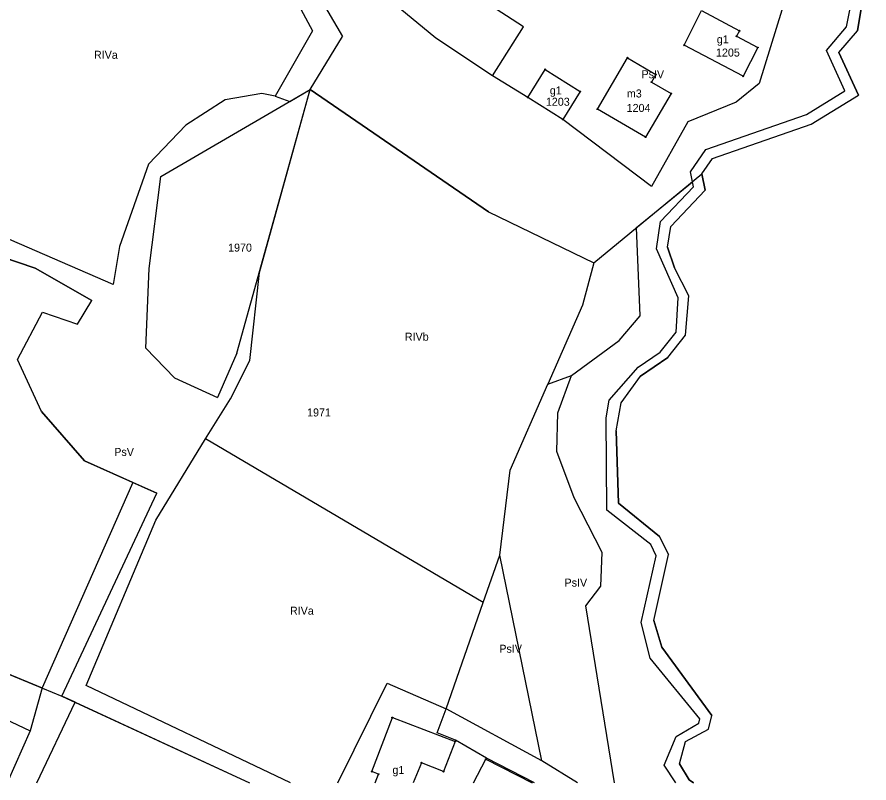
# Model space of a CAD drawing. Extents: x 7498273 to 7499989, y 5499795 to 5500810.
# Drawn here: x 7499569.7 to 7499729.3, y 5499795 to 5499938.6 of the extents above; entities that cross this region are included whole.
import ezdxf

# ---------------------------------------------------------------- set-up
doc = ezdxf.new("R2010")
doc.units = 0
for name, color, linetype in [('209-oznaczenie konturu klasyfikacyjnego', 7, 'Continuous'), ('211-numer działki ewidencyjnej', 7, 'Continuous'), ('217-kontur klasyfikacyjny', 7, 'Continuous'), ('218-kontur użytku gruntowego', 7, 'Continuous'), ('219-działka ewidencyjna', 7, 'Continuous'), ('312-budynek ewidencyjny', 7, 'Continuous'), ('312-oznaczenie budynku ewidencyjnego', 7, 'Continuous'), ('312-oznaczenie budynku ewidencyjnego-Atr117', 7, 'Continuous'), ('Punkt budynku', 7, 'Continuous')]:
    doc.layers.add(name, color=color, linetype=linetype)

# ---------------------------------------------------------------- blocks, each defined once
blk = doc.blocks.new('PUNKTBUD')
blk.add_circle((0, 0), 0.09)

msp = doc.modelspace()

# ---------------------------------------------------------------- linework, layer by layer
at = {"layer": '217-kontur klasyfikacyjny'}
for points in [[(7499648.19, 5499934.62), (7499630.46, 5499949.31)], [(7499619.31, 5499946.76), (7499625.09, 5499936)], [(7499725.13, 5499936.77), (7499727.33, 5499947.8)], [(7499714.09, 5499943.34), (7499708.75, 5499926.13)], [(7499664.64, 5499936.76), (7499657.35, 5499941.41)], [(7499625.09, 5499936), (7499618.09, 5499923.72)], [(7499658.78, 5499927.57), (7499664.64, 5499936.76)], [(7499721.37, 5499932.28), (7499725.13, 5499936.77)], [(7499658.78, 5499927.57), (7499648.19, 5499934.62)], [(7499724.82, 5499924.72), (7499721.37, 5499932.28)], [(7499665.4, 5499923.52), (7499658.78, 5499927.57)], [(7499708.75, 5499926.13), (7499704.45, 5499922.6)], [(7499615.13, 5499890.72), (7499624.67, 5499924.98)], [(7499620.84, 5499922.74), (7499624.67, 5499924.98)], [(7499624.67, 5499924.98), (7499658.04, 5499902.06)], [(7499717.64, 5499920.32), (7499724.82, 5499924.72)], [(7499608.7, 5499923.03), (7499601.35, 5499918.29)], [(7499615.6, 5499924.27), (7499608.7, 5499923.03)], [(7499618.09, 5499923.72), (7499615.6, 5499924.27)], [(7499618.09, 5499923.72), (7499620.84, 5499922.74)], [(7499671.96, 5499919.4), (7499665.4, 5499923.52)], [(7499704.45, 5499922.6), (7499695.4, 5499918.96)], [(7499698.76, 5499913.76), (7499717.64, 5499920.32)], [(7499601.35, 5499918.29), (7499594.38, 5499910.98)], [(7499688.59, 5499906.81), (7499671.96, 5499919.4)], [(7499695.4, 5499918.96), (7499688.59, 5499906.81)], [(7499695.9, 5499909.59), (7499698.76, 5499913.76)], [(7499594.38, 5499910.98), (7499588.91, 5499895.59)], [(7499587.74, 5499888.42), (7499541.18, 5499908.6)], [(7499696.28, 5499907.72), (7499695.9, 5499909.59)], [(7499685.77, 5499899.1), (7499696.28, 5499907.72)], [(7499690.31, 5499900.23), (7499696.48, 5499906.73)], [(7499696.48, 5499906.73), (7499696.28, 5499907.72)], [(7499573.12, 5499891.48), (7499539.45, 5499902.93)], [(7499658.04, 5499902.06), (7499677.77, 5499892.53)], [(7499686.48, 5499882.57), (7499685.77, 5499899.1)], [(7499689.51, 5499895.15), (7499690.31, 5499900.23)], [(7499588.91, 5499895.59), (7499587.74, 5499888.42)], [(7499693.57, 5499885.92), (7499689.51, 5499895.15)], [(7499677.77, 5499892.53), (7499675.65, 5499884.59)], [(7499583.71, 5499885.47), (7499573.12, 5499891.48)], [(7499613.32, 5499874.2), (7499615.13, 5499890.72)], [(7499581.03, 5499881.03), (7499583.71, 5499885.47)], [(7499675.65, 5499884.59), (7499669.19, 5499869.78)], [(7499693.24, 5499879.54), (7499693.57, 5499885.92)], [(7499569.8, 5499874.38), (7499574.48, 5499883.26)], [(7499574.48, 5499883.26), (7499581.03, 5499881.03)], [(7499682.52, 5499877.93), (7499686.48, 5499882.57)], [(7499690.19, 5499875.78), (7499693.24, 5499879.54)], [(7499673.63, 5499871.37), (7499682.52, 5499877.93)], [(7499686.12, 5499872.95), (7499690.19, 5499875.78)], [(7499574.28, 5499864.67), (7499569.8, 5499874.38)], [(7499609.74, 5499867.02), (7499613.32, 5499874.2)], [(7499680.66, 5499866.74), (7499686.12, 5499872.95)], [(7499669.19, 5499869.78), (7499673.63, 5499871.37)], [(7499671.07, 5499864.41), (7499673.63, 5499871.37)], [(7499662.14, 5499853.62), (7499669.19, 5499869.78)], [(7499605.01, 5499859.51), (7499609.74, 5499867.02)], [(7499680.08, 5499863.45), (7499680.66, 5499866.74)], [(7499582.37, 5499855.38), (7499574.28, 5499864.67)], [(7499670.85, 5499857.16), (7499671.07, 5499864.41)], [(7499680.23, 5499846.13), (7499680.08, 5499863.45)], [(7499595.75, 5499844.25), (7499605.01, 5499859.51)], [(7499657.07, 5499828.84), (7499605.01, 5499859.51)], [(7499674.09, 5499848.47), (7499670.85, 5499857.16)], [(7499591.42, 5499851.33), (7499582.37, 5499855.38)], [(7499660.19, 5499837.72), (7499662.14, 5499853.62)], [(7499591.42, 5499851.33), (7499574.43, 5499812.83)], [(7499595.91, 5499849.32), (7499591.42, 5499851.33)], [(7499578.1, 5499811.31), (7499595.91, 5499849.32)], [(7499679.34, 5499838.24), (7499674.09, 5499848.47)], [(7499688.48, 5499839.69), (7499680.23, 5499846.13)], [(7499582.65, 5499813.28), (7499595.75, 5499844.25)], [(7499689.49, 5499837.61), (7499688.48, 5499839.69)], [(7499679.13, 5499831.88), (7499679.34, 5499838.24)], [(7499657.07, 5499828.84), (7499660.19, 5499837.72)], [(7499668.06, 5499799.14), (7499660.19, 5499837.72)], [(7499686.68, 5499825.09), (7499689.49, 5499837.61)], [(7499521.93, 5499834.54), (7499574.43, 5499812.83)], [(7499676.29, 5499828.22), (7499679.13, 5499831.88)], [(7499650.11, 5499808.89), (7499657.07, 5499828.84)], [(7499681.644, 5499795.022), (7499676.29, 5499828.22)], [(7499688.32, 5499818.43), (7499686.68, 5499825.09)], [(7499697.64, 5499807.05), (7499688.32, 5499818.43)], [(7499574.43, 5499812.83), (7499572.2, 5499804.78)], [(7499620.978, 5499795.022), (7499582.65, 5499813.28)], [(7499629.827, 5499795.022), (7499639.06, 5499813.7)], [(7499639.06, 5499813.7), (7499650.11, 5499808.89)], [(7499580.61, 5499810.15), (7499578.1, 5499811.31)], [(7499573.431, 5499795.022), (7499580.61, 5499810.15)], [(7499580.61, 5499810.15), (7499613.262, 5499795.022)], [(7499563.66, 5499808.78), (7499572.2, 5499804.78)], [(7499648.44, 5499804.42), (7499650.11, 5499808.89)], [(7499668.06, 5499799.14), (7499650.11, 5499808.89)], [(7499693.23, 5499803.74), (7499697.48, 5499806.2)], [(7499697.48, 5499806.2), (7499697.64, 5499807.05)], [(7499572.2, 5499804.78), (7499567.876, 5499795.022)], [(7499651.89, 5499803.04), (7499648.44, 5499804.42)], [(7499657.69, 5499799.64), (7499651.89, 5499803.04)], [(7499691, 5499798.35), (7499693.23, 5499803.74)], [(7499666.683, 5499795.022), (7499657.69, 5499799.64)], [(7499674.723, 5499795.022), (7499668.06, 5499799.14)], [(7499693.185, 5499795.022), (7499691, 5499798.35)]]:
    msp.add_lwpolyline(points, dxfattribs=at)
at = {"layer": '218-kontur użytku gruntowego'}
for points in [[(7499648.19, 5499934.62), (7499630.46, 5499949.31)], [(7499727.2, 5499936.01), (7499729.34, 5499948.99)], [(7499619.31, 5499946.76), (7499625.09, 5499936)], [(7499725.13, 5499936.77), (7499727.33, 5499947.8)], [(7499714.09, 5499943.34), (7499708.75, 5499926.13)], [(7499664.64, 5499936.76), (7499657.35, 5499941.41)], [(7499625.09, 5499936), (7499618.09, 5499923.72)], [(7499658.78, 5499927.57), (7499664.64, 5499936.76)], [(7499721.37, 5499932.28), (7499725.13, 5499936.77)], [(7499723.71, 5499931.96), (7499727.2, 5499936.01)], [(7499658.78, 5499927.57), (7499648.19, 5499934.62)], [(7499724.82, 5499924.72), (7499721.37, 5499932.28)], [(7499727.38, 5499923.94), (7499723.71, 5499931.96)], [(7499665.4, 5499923.52), (7499658.78, 5499927.57)], [(7499708.75, 5499926.13), (7499704.45, 5499922.6)], [(7499615.13, 5499890.72), (7499624.67, 5499924.98)], [(7499620.84, 5499922.74), (7499624.67, 5499924.98)], [(7499624.67, 5499924.98), (7499658.04, 5499902.06)], [(7499717.64, 5499920.32), (7499724.82, 5499924.72)], [(7499608.7, 5499923.03), (7499601.35, 5499918.29)], [(7499615.6, 5499924.27), (7499608.7, 5499923.03)], [(7499618.09, 5499923.72), (7499615.6, 5499924.27)], [(7499618.09, 5499923.72), (7499620.84, 5499922.74)], [(7499671.96, 5499919.4), (7499665.4, 5499923.52)], [(7499718.5, 5499918.5), (7499727.38, 5499923.94)], [(7499704.45, 5499922.6), (7499695.4, 5499918.96)], [(7499698.76, 5499913.76), (7499717.64, 5499920.32)], [(7499601.35, 5499918.29), (7499594.38, 5499910.98)], [(7499688.59, 5499906.81), (7499671.96, 5499919.4)], [(7499695.4, 5499918.96), (7499688.59, 5499906.81)], [(7499700.04, 5499912.09), (7499718.5, 5499918.5)], [(7499695.9, 5499909.59), (7499698.76, 5499913.76)], [(7499698.03, 5499909.16), (7499700.04, 5499912.09)], [(7499594.38, 5499910.98), (7499588.91, 5499895.59)], [(7499587.74, 5499888.42), (7499541.18, 5499908.6)], [(7499696.28, 5499907.72), (7499695.9, 5499909.59)], [(7499698.65, 5499906.11), (7499698.03, 5499909.16)], [(7499685.77, 5499899.1), (7499696.28, 5499907.72)], [(7499690.31, 5499900.23), (7499696.48, 5499906.73)], [(7499696.48, 5499906.73), (7499696.28, 5499907.72)], [(7499692.19, 5499899.3), (7499698.65, 5499906.11)], [(7499573.12, 5499891.48), (7499539.45, 5499902.93)], [(7499658.04, 5499902.06), (7499677.77, 5499892.53)], [(7499686.48, 5499882.57), (7499685.77, 5499899.1)], [(7499689.51, 5499895.15), (7499690.31, 5499900.23)], [(7499691.58, 5499895.42), (7499692.19, 5499899.3)], [(7499588.91, 5499895.59), (7499587.74, 5499888.42)], [(7499693.57, 5499885.92), (7499689.51, 5499895.15)], [(7499692.92, 5499891.59), (7499691.58, 5499895.42)], [(7499677.77, 5499892.53), (7499675.65, 5499884.59)], [(7499583.71, 5499885.47), (7499573.12, 5499891.48)], [(7499695.6, 5499886.35), (7499692.92, 5499891.59)], [(7499613.32, 5499874.2), (7499615.13, 5499890.72)], [(7499694.96, 5499878.95), (7499695.6, 5499886.35)], [(7499581.03, 5499881.03), (7499583.71, 5499885.47)], [(7499675.65, 5499884.59), (7499669.19, 5499869.78)], [(7499693.24, 5499879.54), (7499693.57, 5499885.92)], [(7499569.8, 5499874.38), (7499574.48, 5499883.26)], [(7499574.48, 5499883.26), (7499581.03, 5499881.03)], [(7499682.52, 5499877.93), (7499686.48, 5499882.57)], [(7499690.19, 5499875.78), (7499693.24, 5499879.54)], [(7499691.68, 5499874.79), (7499694.96, 5499878.95)], [(7499673.63, 5499871.37), (7499682.52, 5499877.93)], [(7499686.12, 5499872.95), (7499690.19, 5499875.78)], [(7499574.28, 5499864.67), (7499569.8, 5499874.38)], [(7499609.74, 5499867.02), (7499613.32, 5499874.2)], [(7499686.55, 5499871.28), (7499691.68, 5499874.79)], [(7499680.66, 5499866.74), (7499686.12, 5499872.95)], [(7499669.19, 5499869.78), (7499673.63, 5499871.37)], [(7499671.07, 5499864.41), (7499673.63, 5499871.37)], [(7499682.89, 5499866.26), (7499686.55, 5499871.28)], [(7499662.14, 5499853.62), (7499669.19, 5499869.78)], [(7499605.01, 5499859.51), (7499609.74, 5499867.02)], [(7499680.08, 5499863.45), (7499680.66, 5499866.74)], [(7499681.97, 5499861), (7499682.89, 5499866.26)], [(7499582.37, 5499855.38), (7499574.28, 5499864.67)], [(7499670.85, 5499857.16), (7499671.07, 5499864.41)], [(7499680.23, 5499846.13), (7499680.08, 5499863.45)], [(7499682.39, 5499847.48), (7499681.97, 5499861)], [(7499595.75, 5499844.25), (7499605.01, 5499859.51)], [(7499657.07, 5499828.84), (7499605.01, 5499859.51)], [(7499674.09, 5499848.47), (7499670.85, 5499857.16)], [(7499591.42, 5499851.33), (7499582.37, 5499855.38)], [(7499660.19, 5499837.72), (7499662.14, 5499853.62)], [(7499591.42, 5499851.33), (7499574.43, 5499812.83)], [(7499595.91, 5499849.32), (7499591.42, 5499851.33)], [(7499578.1, 5499811.31), (7499595.91, 5499849.32)], [(7499679.34, 5499838.24), (7499674.09, 5499848.47)], [(7499688.48, 5499839.69), (7499680.23, 5499846.13)], [(7499690.12, 5499841.2), (7499682.39, 5499847.48)], [(7499582.65, 5499813.28), (7499595.75, 5499844.25)], [(7499689.49, 5499837.61), (7499688.48, 5499839.69)], [(7499691.8, 5499837.85), (7499690.12, 5499841.2)], [(7499679.13, 5499831.88), (7499679.34, 5499838.24)], [(7499657.07, 5499828.84), (7499660.19, 5499837.72)], [(7499668.06, 5499799.14), (7499660.19, 5499837.72)], [(7499686.68, 5499825.09), (7499689.49, 5499837.61)], [(7499689.06, 5499825.46), (7499691.8, 5499837.85)], [(7499521.93, 5499834.54), (7499574.43, 5499812.83)], [(7499676.29, 5499828.22), (7499679.13, 5499831.88)], [(7499650.11, 5499808.89), (7499657.07, 5499828.84)], [(7499681.644, 5499795.022), (7499676.29, 5499828.22)], [(7499690.54, 5499820.49), (7499689.06, 5499825.46)], [(7499688.32, 5499818.43), (7499686.68, 5499825.09)], [(7499699.93, 5499807.67), (7499690.54, 5499820.49)], [(7499697.64, 5499807.05), (7499688.32, 5499818.43)], [(7499574.43, 5499812.83), (7499572.2, 5499804.78)], [(7499620.978, 5499795.022), (7499582.65, 5499813.28)], [(7499629.827, 5499795.022), (7499639.06, 5499813.7)], [(7499639.06, 5499813.7), (7499650.11, 5499808.89)], [(7499580.61, 5499810.15), (7499578.1, 5499811.31)], [(7499573.431, 5499795.022), (7499580.61, 5499810.15)], [(7499580.61, 5499810.15), (7499613.262, 5499795.022)], [(7499563.66, 5499808.78), (7499572.2, 5499804.78)], [(7499648.44, 5499804.42), (7499650.11, 5499808.89)], [(7499668.06, 5499799.14), (7499650.11, 5499808.89)], [(7499693.23, 5499803.74), (7499697.48, 5499806.2)], [(7499697.48, 5499806.2), (7499697.64, 5499807.05)], [(7499699.29, 5499805.08), (7499699.93, 5499807.67)], [(7499572.2, 5499804.78), (7499567.876, 5499795.022)], [(7499694.94, 5499802.77), (7499699.29, 5499805.08)], [(7499651.89, 5499803.04), (7499648.44, 5499804.42)], [(7499657.69, 5499799.64), (7499651.89, 5499803.04)], [(7499691, 5499798.35), (7499693.23, 5499803.74)], [(7499693.87, 5499798.62), (7499694.94, 5499802.77)], [(7499666.683, 5499795.022), (7499657.69, 5499799.64)], [(7499674.723, 5499795.022), (7499668.06, 5499799.14)], [(7499693.185, 5499795.022), (7499691, 5499798.35)], [(7499695.68, 5499795.59), (7499693.87, 5499798.62)], [(7499696.479, 5499795.022), (7499695.68, 5499795.59)]]:
    msp.add_lwpolyline(points, dxfattribs=at)
at = {"layer": '219-działka ewidencyjna'}
for points in [[(7499622.43, 5499949.02), (7499630.7, 5499934.9)], [(7499729.34, 5499948.99), (7499727.2, 5499936.01)], [(7499723.71, 5499931.96), (7499727.2, 5499936.01)], [(7499624.67, 5499924.98), (7499630.7, 5499934.9)], [(7499723.71, 5499931.96), (7499727.38, 5499923.94)], [(7499596.69, 5499908.66), (7499624.67, 5499924.98)], [(7499610.91, 5499875.57), (7499624.67, 5499924.98)], [(7499658.04, 5499902.06), (7499624.67, 5499924.98)], [(7499718.5, 5499918.5), (7499727.38, 5499923.94)], [(7499700.04, 5499912.09), (7499718.5, 5499918.5)], [(7499698.03, 5499909.16), (7499700.04, 5499912.09)], [(7499594.48, 5499891.43), (7499596.69, 5499908.66)], [(7499677.77, 5499892.53), (7499698.03, 5499909.16)], [(7499698.03, 5499909.16), (7499698.65, 5499906.11)], [(7499692.19, 5499899.3), (7499698.65, 5499906.11)], [(7499535.88, 5499904.15), (7499573.12, 5499891.48)], [(7499658.04, 5499902.06), (7499677.77, 5499892.53)], [(7499691.58, 5499895.42), (7499692.19, 5499899.3)], [(7499691.58, 5499895.42), (7499692.92, 5499891.59)], [(7499573.12, 5499891.48), (7499583.71, 5499885.47)], [(7499593.86, 5499876.51), (7499594.48, 5499891.43)], [(7499695.6, 5499886.35), (7499692.92, 5499891.59)], [(7499694.96, 5499878.95), (7499695.6, 5499886.35)], [(7499581.03, 5499881.03), (7499583.71, 5499885.47)], [(7499569.8, 5499874.38), (7499574.48, 5499883.26)], [(7499574.48, 5499883.26), (7499581.03, 5499881.03)], [(7499691.68, 5499874.79), (7499694.96, 5499878.95)], [(7499593.86, 5499876.51), (7499599.2, 5499870.96)], [(7499610.91, 5499875.57), (7499607.29, 5499867.24)], [(7499574.28, 5499864.67), (7499569.8, 5499874.38)], [(7499691.68, 5499874.79), (7499686.55, 5499871.28)], [(7499599.2, 5499870.96), (7499607.29, 5499867.24)], [(7499682.89, 5499866.26), (7499686.55, 5499871.28)], [(7499681.97, 5499861), (7499682.89, 5499866.26)], [(7499574.28, 5499864.67), (7499582.37, 5499855.38)], [(7499681.97, 5499861), (7499682.39, 5499847.48)], [(7499582.37, 5499855.38), (7499595.91, 5499849.32)], [(7499578.1, 5499811.31), (7499595.91, 5499849.32)], [(7499682.39, 5499847.48), (7499690.12, 5499841.2)], [(7499690.12, 5499841.2), (7499691.8, 5499837.85)], [(7499689.06, 5499825.46), (7499691.8, 5499837.85)], [(7499521.93, 5499834.54), (7499578.1, 5499811.31)], [(7499689.06, 5499825.46), (7499690.54, 5499820.49)], [(7499690.54, 5499820.49), (7499699.93, 5499807.67)], [(7499578.1, 5499811.31), (7499613.256, 5499795.022)], [(7499699.29, 5499805.08), (7499699.93, 5499807.67)], [(7499694.94, 5499802.77), (7499699.29, 5499805.08)], [(7499693.87, 5499798.62), (7499694.94, 5499802.77)], [(7499693.87, 5499798.62), (7499695.68, 5499795.59)], [(7499695.68, 5499795.59), (7499696.479, 5499795.022)]]:
    msp.add_lwpolyline(points, dxfattribs=at)
at = {"layer": '312-budynek ewidencyjny'}
for points in [[(7499694.69, 5499933.28), (7499697.97, 5499939.8)], [(7499697.97, 5499939.8), (7499705.09, 5499936.01)], [(7499705.09, 5499936.01), (7499704.54, 5499934.98)], [(7499704.54, 5499934.98), (7499708.5, 5499932.87)], [(7499705.79, 5499927.49), (7499694.69, 5499933.28)], [(7499708.5, 5499932.87), (7499705.79, 5499927.49)], [(7499678.46, 5499921.34), (7499684.12, 5499930.94)], [(7499684.12, 5499930.94), (7499689.43, 5499927.79)], [(7499665.4, 5499923.52), (7499668.65, 5499928.76)], [(7499668.65, 5499928.76), (7499675.24, 5499924.62)], [(7499689.43, 5499927.79), (7499688.59, 5499926.37)], [(7499688.59, 5499926.37), (7499692.31, 5499924.23)], [(7499675.24, 5499924.62), (7499671.96, 5499919.4)], [(7499671.96, 5499919.4), (7499665.4, 5499923.52)], [(7499692.31, 5499924.23), (7499687.49, 5499916.06)], [(7499687.49, 5499916.06), (7499678.46, 5499921.34)], [(7499636.17, 5499797.15), (7499640.04, 5499807.28)], [(7499640.04, 5499807.28), (7499651.81, 5499802.81)], [(7499651.81, 5499802.81), (7499649.6, 5499797.15)], [(7499645.51, 5499798.82), (7499643.953, 5499795.022)], [(7499649.6, 5499797.15), (7499645.51, 5499798.82)], [(7499655.248, 5499795.022), (7499657.57, 5499799.46)], [(7499657.57, 5499799.46), (7499666.262, 5499795.022)], [(7499637.46, 5499796.66), (7499636.17, 5499797.15)], [(7499636.845, 5499795.022), (7499637.46, 5499796.66)]]:
    msp.add_lwpolyline(points, dxfattribs=at)

# ---------------------------------------------------------------- block references
at = {"layer": 'Punkt budynku'}
for p in [(7499705.09, 5499936.01), (7499704.54, 5499934.98), (7499694.69, 5499933.28), (7499708.5, 5499932.87), (7499684.12, 5499930.94), (7499668.65, 5499928.76), (7499689.43, 5499927.79), (7499705.79, 5499927.49), (7499688.59, 5499926.37), (7499675.24, 5499924.62), (7499692.31, 5499924.23), (7499665.4, 5499923.52), (7499678.46, 5499921.34), (7499671.96, 5499919.4), (7499687.49, 5499916.06), (7499640.04, 5499807.28), (7499651.81, 5499802.81), (7499645.51, 5499798.82), (7499657.57, 5499799.46), (7499636.17, 5499797.15), (7499637.46, 5499796.66), (7499649.6, 5499797.15)]:
    msp.add_blockref('PUNKTBUD', p, dxfattribs=at)

# ---------------------------------------------------------------- texts
at = {"layer": '209-oznaczenie konturu klasyfikacyjnego'}
for s, p in [('RIVa', (7499584.14, 5499930.75)), ('PsIV', (7499686.72, 5499927.11)), ('RIVb', (7499642.39, 5499877.91)), ('PsV', (7499587.95, 5499856.32)), ('PsIV', (7499672.3, 5499831.82)), ('RIVa', (7499620.86, 5499826.56)), ('PsIV', (7499660.09, 5499819.43))]:
    msp.add_text(s, height=1.5, dxfattribs=at).set_placement(p)
at = {"layer": '211-numer działki ewidencyjnej'}
for s, p in [('1970', (7499609.27, 5499894.61)), ('1971', (7499624.07, 5499863.72))]:
    msp.add_text(s, height=1.5, dxfattribs=at).set_placement(p)
at = {"layer": '312-oznaczenie budynku ewidencyjnego'}
for s, p in [('1205', (7499700.68, 5499931.17)), ('1203', (7499668.81, 5499921.95)), ('1204', (7499683.94, 5499920.79))]:
    msp.add_text(s, height=1.5, dxfattribs=at).set_placement(p)
at = {"layer": '312-oznaczenie budynku ewidencyjnego-Atr117'}
for s, p in [('g1', (7499700.829, 5499933.65)), ('g1', (7499669.549, 5499924.08)), ('m3', (7499683.976, 5499923.5)), ('g1', (7499640.06, 5499796.71))]:
    msp.add_text(s, height=1.5, dxfattribs=at).set_placement(p)

doc.saveas('drawing.dxf')
